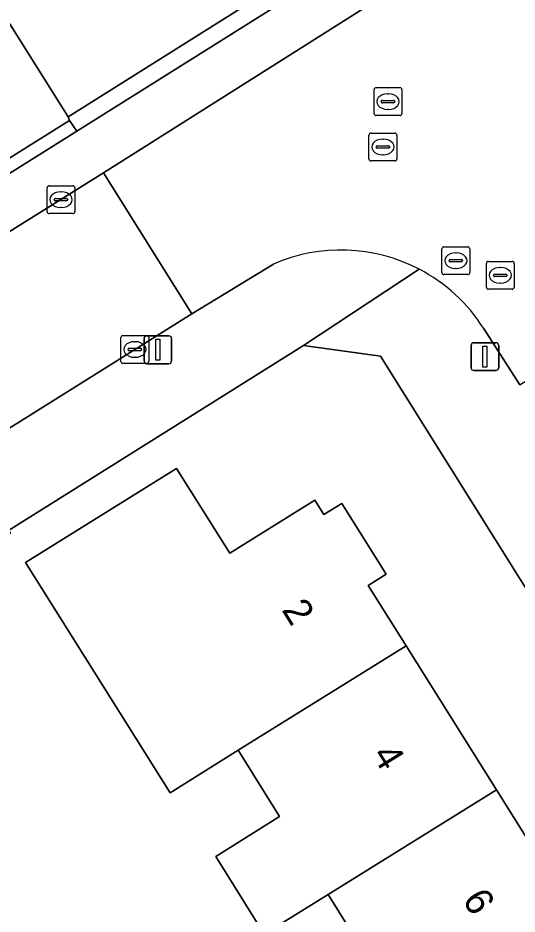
# Model space of a CAD drawing. Extents: x 159352 to 160617, y 385888 to 387323.
# Drawn here: x 159664.19 to 159682.11, y 386145.65 to 386177.82 of the extents above; entities that cross this region are included whole.
import ezdxf

# ---------------------------------------------------------------- set-up
doc = ezdxf.new("R2010")
doc.units = 0
for name, color, linetype in [('IMGEO_Erf', 7, 'Continuous'), ('IMGEO_Groenvoorziening', 7, 'Continuous'), ('IMGEO_Kolk', 7, 'Continuous'), ('IMGEO_Lichtmast', 7, 'Continuous'), ('IMGEO_Pand', 7, 'Continuous'), ('IMGEO_Pand_nummerreeks', 7, 'Continuous'), ('IMGEO_Parkeervlak_open', 7, 'Continuous'), ('IMGEO_Rijbaan_lokaal_open', 7, 'Continuous'), ('IMGEO_Rioolput', 7, 'Continuous'), ('IMGEO_Voetpad_open', 7, 'Continuous')]:
    doc.layers.add(name, color=color, linetype=linetype)

msp = doc.modelspace()

# ---------------------------------------------------------------- linework, layer by layer
at = {"layer": 'IMGEO_Erf'}
for points in [[(159712.934, 386108.61), (159677.208, 386165.677), (159674.448, 386166.054), (159663.861, 386159.423), (159663.923, 386159.326), (159657.127, 386155.101), (159662.969, 386145.784), (159661.381, 386144.772)], [(159678.55, 386141.18), (159675.326, 386146.356), (159673.029, 386144.926), (159671.294, 386147.714), (159673.587, 386149.149), (159672.103, 386151.532), (159669.661, 386150.002), (159664.466, 386158.268), (159669.886, 386161.642), (159671.796, 386158.603), (159674.849, 386160.506), (159675.173, 386159.989), (159675.818, 386160.391), (159677.412, 386157.849), (159676.767, 386157.447), (159678.126, 386155.28), (159681.365, 386150.113), (159684.605, 386144.946)]]:
    msp.add_lwpolyline(points, dxfattribs=at)
at = {"layer": 'IMGEO_Groenvoorziening'}
msp.add_lwpolyline([(159665.998, 386174.271), (159679.843, 386182.982), (159678.601, 386185.01), (159672.385, 386182.329), (159672.791, 386181.378), (159671.129, 386180.658), (159670.692, 386181.586), (159669.578, 386181.115), (159663.38, 386178.426)], close=True, dxfattribs=at)
at = {"layer": 'IMGEO_Kolk'}
for p, q in [((159665.239, 386170.867), (159665.239, 386171.719)), ((159665.314, 386171.793), (159666.166, 386171.793)), ((159665.727, 386171.573), (159665.752, 386171.573)), ((159666.24, 386171.719), (159666.24, 386170.867)), ((159665.498, 386171.287), (159665.498, 386171.299)), ((159665.936, 386171.25), (159665.538, 386171.25)), ((159665.541, 386171.336), (159665.939, 386171.336)), ((159665.982, 386171.299), (159665.982, 386171.287)), ((159665.75, 386171.013), (159665.725, 386171.013)), ((159666.166, 386170.793), (159665.314, 386170.793)), ((159667.89, 386165.49), (159667.89, 386166.342)), ((159667.965, 386166.416), (159668.817, 386166.416)), ((159668.891, 386166.342), (159668.891, 386165.49)), ((159668.378, 386166.196), (159668.403, 386166.196)), ((159668.149, 386165.91), (159668.149, 386165.922)), ((159668.587, 386165.873), (159668.189, 386165.873)), ((159668.192, 386165.959), (159668.59, 386165.959)), ((159668.633, 386165.922), (159668.633, 386165.91)), ((159668.817, 386165.416), (159667.965, 386165.416)), ((159668.401, 386165.636), (159668.376, 386165.636))]:
    msp.add_line(p, q, dxfattribs=at)
for points in [[(159665.239, 386170.867), (159665.239, 386171.719)], [(159665.314, 386171.793), (159666.166, 386171.793)], [(159666.24, 386171.719), (159666.24, 386170.867)], [(159666.166, 386170.793), (159665.314, 386170.793)], [(159667.89, 386165.49), (159667.89, 386166.342)], [(159667.965, 386166.416), (159668.817, 386166.416)], [(159668.891, 386166.342), (159668.891, 386165.49)], [(159668.817, 386165.416), (159667.965, 386165.416)]]:
    msp.add_lwpolyline(points, dxfattribs=at)
for centre, radius, start, end in [((159665.316, 386171.717), 0.0765, 91.552, 178.448), ((159665.316, 386171.717), 0.0765, 91.552, 178.448), ((159666.164, 386171.717), 0.0765, 1.552, 88.448), ((159666.164, 386171.717), 0.0765, 1.552, 88.448), ((159665.538, 386171.296), 0.0403, 85.8775, 175.7526), ((159665.535, 386171.286), 0.0366, 178.938, 274.7102), ((159665.939, 386171.293), 0.043, 264.8664, 352.4533), ((159665.943, 386171.298), 0.0386, 1.7309, 96.639), ((159665.316, 386170.869), 0.0765, 181.552, 268.448), ((159665.316, 386170.869), 0.0765, 181.552, 268.448), ((159666.164, 386170.869), 0.0765, 271.552, 358.448), ((159666.164, 386170.869), 0.0765, 271.552, 358.448), ((159667.967, 386166.34), 0.0765, 91.552, 178.448), ((159667.967, 386166.34), 0.0765, 91.552, 178.448), ((159668.815, 386166.34), 0.0765, 1.552, 88.448), ((159668.815, 386166.34), 0.0765, 1.552, 88.448), ((159668.189, 386165.919), 0.0403, 85.8775, 175.7526), ((159668.186, 386165.909), 0.0366, 178.938, 274.7102), ((159668.59, 386165.916), 0.043, 264.8664, 352.4533), ((159668.594, 386165.921), 0.0386, 1.7309, 96.639), ((159667.967, 386165.492), 0.0765, 181.552, 268.448), ((159667.967, 386165.492), 0.0765, 181.552, 268.448), ((159668.815, 386165.492), 0.0765, 271.552, 358.448), ((159668.815, 386165.492), 0.0765, 271.552, 358.448)]:
    msp.add_arc(centre, radius, start, end, dxfattribs=at)
for centre, major_axis, ratio, start_param, end_param in [((159665.726, 386171.293), (-0.387, 0.002), 0.722429, 4.712389, 7.853982), ((159665.751, 386171.293), (-0.39, 0.002), 0.717154, 1.570796, 4.712389), ((159668.377, 386165.916), (-0.387, 0.002), 0.722429, 4.712389, 7.853982), ((159668.402, 386165.916), (-0.39, 0.002), 0.717154, 1.570796, 4.712389)]:
    msp.add_ellipse(centre, major_axis=major_axis, ratio=ratio, start_param=start_param, end_param=end_param, dxfattribs=at)
at = {"layer": 'IMGEO_Lichtmast'}
for p, q in [((159668.82, 386166.407), (159669.61, 386166.407)), ((159669.61, 386166.407), (159668.82, 386166.407)), ((159668.72, 386165.507), (159668.72, 386166.307)), ((159668.72, 386166.307), (159668.72, 386165.507)), ((159669.71, 386166.307), (159669.71, 386165.507)), ((159669.71, 386165.507), (159669.71, 386166.307)), ((159680.459, 386165.261), (159680.459, 386166.061)), ((159680.459, 386166.061), (159680.459, 386165.261)), ((159680.559, 386166.161), (159681.349, 386166.161)), ((159681.349, 386166.161), (159680.559, 386166.161)), ((159681.449, 386166.061), (159681.449, 386165.261)), ((159681.449, 386165.261), (159681.449, 386166.061)), ((159669.61, 386165.407), (159668.82, 386165.407)), ((159668.82, 386165.407), (159669.61, 386165.407)), ((159681.349, 386165.161), (159680.559, 386165.161)), ((159680.559, 386165.161), (159681.349, 386165.161))]:
    msp.add_line(p, q, dxfattribs=at)
for points in [[(159669.14, 386166.282), (159669.29, 386166.282), (159669.29, 386165.532), (159669.14, 386165.532), (159669.14, 386166.282)], [(159680.879, 386166.036), (159681.029, 386166.036), (159681.029, 386165.286), (159680.879, 386165.286), (159680.879, 386166.036)]]:
    msp.add_lwpolyline(points, dxfattribs=at)
for centre, start, end in [((159668.82, 386166.307), 90, 180), ((159668.82, 386166.307), 90, 180), ((159669.61, 386166.307), 0, 90), ((159669.61, 386166.307), 360, 90), ((159680.559, 386166.061), 90, 180), ((159680.559, 386166.061), 90, 180), ((159681.349, 386166.061), 0, 90), ((159681.349, 386166.061), 360, 90), ((159668.82, 386165.507), 180, 270), ((159668.82, 386165.507), 180, 270), ((159669.61, 386165.507), 270, 0), ((159669.61, 386165.507), 270, 0), ((159680.559, 386165.261), 180, 270), ((159680.559, 386165.261), 180, 270), ((159681.349, 386165.261), 270, 0), ((159681.349, 386165.261), 270, 0)]:
    msp.add_arc(centre, 0.1, start, end, dxfattribs=at)
at = {"layer": 'IMGEO_Pand'}
for points in [[(159678.126, 386155.28), (159676.767, 386157.447), (159677.412, 386157.849), (159675.818, 386160.391), (159675.173, 386159.989), (159674.849, 386160.506), (159671.796, 386158.603), (159669.886, 386161.642), (159664.466, 386158.268), (159669.661, 386150.002), (159672.103, 386151.532)], [(159681.365, 386150.113), (159678.126, 386155.28), (159672.103, 386151.532), (159673.587, 386149.149), (159671.294, 386147.714), (159673.029, 386144.926), (159675.326, 386146.356)], [(159675.326, 386146.356), (159678.55, 386141.18), (159684.605, 386144.946), (159681.365, 386150.113)]]:
    msp.add_lwpolyline(points, close=True, dxfattribs=at)
at = {"layer": 'IMGEO_Parkeervlak_open'}
for points in [[(159694.982, 386191.739), (159692.137, 386189.957), (159683.351, 386184.43), (159680.171, 386182.463), (159666.308, 386173.758), (159663.117, 386171.76), (159649.085, 386162.993), (159645.879, 386160.999), (159629.498, 386150.732), (159629.323, 386150.614)], [(159667.269, 386172.261), (159686.801, 386184.624), (159698.284, 386191.67)], [(159628.085, 386147.762), (159667.269, 386172.261)]]:
    msp.add_lwpolyline(points, dxfattribs=at)
at = {"layer": 'IMGEO_Rijbaan_lokaal_open'}
for points in [[(159685.663, 386176.667), (159690.037, 386179.433), (159686.801, 386184.624), (159667.269, 386172.261), (159670.441, 386167.202), (159673.365, 386168.979)], [(159680.899, 386166.685), (159682.211, 386164.651), (159685.102, 386166.476), (159683.833, 386168.497)]]:
    msp.add_lwpolyline(points, dxfattribs=at)
msp.add_lwpolyline([(159648.997, 386153.776), (159651.127, 386155.109), (159653.753, 386156.753), (159670.441, 386167.202), (159667.269, 386172.261), (159628.085, 386147.762), (159631.34, 386142.72), (159646.177, 386152.01)], close=True, dxfattribs=at)
for centre, radius, start, end in [((159675.792, 386163.428), 6.059, 62.3802, 113.6164), ((159675.787, 386163.426), 6.063, 32.5164, 62.3409)]:
    msp.add_arc(centre, radius, start, end, dxfattribs=at)
at = {"layer": 'IMGEO_Rioolput'}
for p, q in [((159676.976, 386174.39), (159676.976, 386175.242)), ((159677.051, 386175.316), (159677.903, 386175.316)), ((159677.464, 386175.096), (159677.489, 386175.096)), ((159677.977, 386175.242), (159677.977, 386174.39)), ((159677.235, 386174.81), (159677.235, 386174.822)), ((159677.673, 386174.773), (159677.275, 386174.773)), ((159677.278, 386174.859), (159677.676, 386174.859)), ((159677.719, 386174.822), (159677.719, 386174.81)), ((159677.487, 386174.536), (159677.462, 386174.536)), ((159677.903, 386174.316), (159677.051, 386174.316)), ((159676.794, 386172.758), (159676.794, 386173.61)), ((159676.869, 386173.684), (159677.721, 386173.684)), ((159677.282, 386173.464), (159677.307, 386173.464)), ((159677.795, 386173.61), (159677.795, 386172.758)), ((159677.053, 386173.178), (159677.053, 386173.19)), ((159677.491, 386173.141), (159677.093, 386173.141)), ((159677.096, 386173.227), (159677.494, 386173.227)), ((159677.537, 386173.19), (159677.537, 386173.178)), ((159677.305, 386172.904), (159677.28, 386172.904)), ((159677.721, 386172.684), (159676.869, 386172.684)), ((159679.486, 386169.604), (159680.338, 386169.604)), ((159679.411, 386168.678), (159679.411, 386169.53)), ((159679.899, 386169.384), (159679.924, 386169.384)), ((159680.412, 386169.53), (159680.412, 386168.678)), ((159679.67, 386169.098), (159679.67, 386169.11)), ((159680.108, 386169.061), (159679.71, 386169.061)), ((159679.713, 386169.147), (159680.111, 386169.147)), ((159680.154, 386169.11), (159680.154, 386169.098)), ((159681.006, 386168.154), (159681.006, 386169.006)), ((159681.081, 386169.08), (159681.933, 386169.08)), ((159682.007, 386169.006), (159682.007, 386168.154)), ((159680.338, 386168.604), (159679.486, 386168.604)), ((159679.922, 386168.824), (159679.897, 386168.824)), ((159681.308, 386168.623), (159681.706, 386168.623)), ((159681.494, 386168.86), (159681.519, 386168.86)), ((159681.265, 386168.574), (159681.265, 386168.586)), ((159681.703, 386168.537), (159681.305, 386168.537)), ((159681.517, 386168.3), (159681.492, 386168.3)), ((159681.749, 386168.586), (159681.749, 386168.574)), ((159681.933, 386168.08), (159681.081, 386168.08))]:
    msp.add_line(p, q, dxfattribs=at)
for points in [[(159676.976, 386174.39), (159676.976, 386175.242)], [(159677.051, 386175.316), (159677.903, 386175.316)], [(159677.977, 386175.242), (159677.977, 386174.39)], [(159677.903, 386174.316), (159677.051, 386174.316)], [(159676.794, 386172.758), (159676.794, 386173.61)], [(159676.869, 386173.684), (159677.721, 386173.684)], [(159677.795, 386173.61), (159677.795, 386172.758)], [(159677.721, 386172.684), (159676.869, 386172.684)], [(159679.486, 386169.604), (159680.338, 386169.604)], [(159679.411, 386168.678), (159679.411, 386169.53)], [(159680.412, 386169.53), (159680.412, 386168.678)], [(159681.006, 386168.154), (159681.006, 386169.006)], [(159681.081, 386169.08), (159681.933, 386169.08)], [(159682.007, 386169.006), (159682.007, 386168.154)], [(159680.338, 386168.604), (159679.486, 386168.604)], [(159681.933, 386168.08), (159681.081, 386168.08)]]:
    msp.add_lwpolyline(points, dxfattribs=at)
for centre, radius, start, end in [((159677.053, 386175.24), 0.0765, 91.552, 178.448), ((159677.053, 386175.24), 0.0765, 91.552, 178.448), ((159677.901, 386175.24), 0.0765, 1.552, 88.448), ((159677.901, 386175.24), 0.0765, 1.552, 88.448), ((159677.275, 386174.819), 0.0403, 85.8775, 175.7526), ((159677.272, 386174.809), 0.0366, 178.938, 274.7102), ((159677.676, 386174.816), 0.043, 264.8664, 352.4533), ((159677.68, 386174.821), 0.0386, 1.7309, 96.639), ((159677.053, 386174.392), 0.0765, 181.552, 268.448), ((159677.053, 386174.392), 0.0765, 181.552, 268.448), ((159677.901, 386174.392), 0.0765, 271.552, 358.448), ((159677.901, 386174.392), 0.0765, 271.552, 358.448), ((159676.871, 386173.608), 0.0765, 91.552, 178.448), ((159676.871, 386173.608), 0.0765, 91.552, 178.448), ((159677.719, 386173.608), 0.0765, 1.552, 88.448), ((159677.719, 386173.608), 0.0765, 1.552, 88.448), ((159677.093, 386173.187), 0.0403, 85.8775, 175.7526), ((159677.09, 386173.177), 0.0366, 178.938, 274.7102), ((159677.494, 386173.184), 0.043, 264.8664, 352.4533), ((159677.498, 386173.189), 0.0386, 1.7309, 96.639), ((159676.871, 386172.76), 0.0765, 181.552, 268.448), ((159676.871, 386172.76), 0.0765, 181.552, 268.448), ((159677.719, 386172.76), 0.0765, 271.552, 358.448), ((159677.719, 386172.76), 0.0765, 271.552, 358.448), ((159679.488, 386169.528), 0.0765, 91.552, 178.448), ((159679.488, 386169.528), 0.0765, 91.552, 178.448), ((159680.336, 386169.528), 0.0765, 1.552, 88.448), ((159680.336, 386169.528), 0.0765, 1.552, 88.448), ((159679.71, 386169.107), 0.0403, 85.8775, 175.7526), ((159679.707, 386169.097), 0.0366, 178.938, 274.7102), ((159680.111, 386169.104), 0.043, 264.8664, 352.4533), ((159680.115, 386169.109), 0.0386, 1.7309, 96.639), ((159681.083, 386169.004), 0.0765, 91.552, 178.448), ((159681.083, 386169.004), 0.0765, 91.552, 178.448), ((159681.931, 386169.004), 0.0765, 1.552, 88.448), ((159681.931, 386169.004), 0.0765, 1.552, 88.448), ((159679.488, 386168.68), 0.0765, 181.552, 268.448), ((159679.488, 386168.68), 0.0765, 181.552, 268.448), ((159680.336, 386168.68), 0.0765, 271.552, 358.448), ((159680.336, 386168.68), 0.0765, 271.552, 358.448), ((159681.305, 386168.583), 0.0403, 85.8775, 175.7526), ((159681.71, 386168.585), 0.0386, 1.7309, 96.639), ((159681.302, 386168.573), 0.0366, 178.938, 274.7102), ((159681.706, 386168.58), 0.043, 264.8664, 352.4533), ((159681.083, 386168.156), 0.0765, 181.552, 268.448), ((159681.083, 386168.156), 0.0765, 181.552, 268.448), ((159681.931, 386168.156), 0.0765, 271.552, 358.448), ((159681.931, 386168.156), 0.0765, 271.552, 358.448)]:
    msp.add_arc(centre, radius, start, end, dxfattribs=at)
for centre, major_axis, ratio, start_param, end_param in [((159677.463, 386174.816), (-0.387, 0.002), 0.722429, 4.712389, 7.853982), ((159677.488, 386174.816), (-0.39, 0.002), 0.717154, 1.570796, 4.712389), ((159677.281, 386173.184), (-0.387, 0.002), 0.722429, 4.712389, 7.853982), ((159677.306, 386173.184), (-0.39, 0.002), 0.717154, 1.570796, 4.712389), ((159679.898, 386169.104), (-0.387, 0.002), 0.722429, 4.712389, 7.853982), ((159679.923, 386169.104), (-0.39, 0.002), 0.717154, 1.570796, 4.712389), ((159681.493, 386168.58), (-0.387, 0.002), 0.722429, 4.712389, 7.853982), ((159681.518, 386168.58), (-0.39, 0.002), 0.717154, 1.570796, 4.712389)]:
    msp.add_ellipse(centre, major_axis=major_axis, ratio=ratio, start_param=start_param, end_param=end_param, dxfattribs=at)
at = {"layer": 'IMGEO_Voetpad_open'}
for points in [[(159662.86, 386172.145), (159666.048, 386174.133), (159665.998, 386174.271), (159663.38, 386178.426), (159669.578, 386181.115), (159670.692, 386181.586), (159671.129, 386180.658), (159672.791, 386181.378), (159672.385, 386182.329), (159678.601, 386185.01), (159679.843, 386182.982), (159679.947, 386182.816), (159683.126, 386184.832), (159683.351, 386184.43), (159692.137, 386189.957), (159691.793, 386190.467), (159685.357, 386186.443), (159684.781, 386187.668), (159691.207, 386190.458), (159698.352, 386193.525), (159698.969, 386192.653), (159702.158, 386194.63), (159702.417, 386194.251), (159725.377, 386208.588)], [(159673.365, 386168.979), (159670.441, 386167.202), (159653.753, 386156.753), (159654.266, 386155.932), (159651.638, 386154.291), (159651.127, 386155.109), (159648.997, 386153.776), (159649.507, 386152.96), (159646.684, 386151.198), (159646.177, 386152.01), (159631.34, 386142.72), (159628.856, 386141.148), (159626.028, 386139.36)], [(159657.127, 386155.101), (159663.923, 386159.326), (159663.861, 386159.423), (159674.448, 386166.054), (159678.601, 386168.796)], [(159678.601, 386168.796), (159674.448, 386166.054), (159677.208, 386165.677), (159712.934, 386108.61), (159713.923, 386107.031), (159717.083, 386101.983), (159727.834, 386084.857), (159727.06, 386082.254), (159731.503, 386085.122)], [(159682.211, 386164.651), (159680.899, 386166.685)]]:
    msp.add_lwpolyline(points, dxfattribs=at)
for points in [[(159680.171, 386182.463), (159679.947, 386182.816), (159679.843, 386182.982), (159665.998, 386174.271), (159666.048, 386174.133), (159666.308, 386173.758)], [(159663.117, 386171.76), (159666.308, 386173.758), (159666.048, 386174.133), (159662.86, 386172.145)]]:
    msp.add_lwpolyline(points, close=True, dxfattribs=at)
for centre, radius, start, end in [((159675.792, 386163.428), 6.059, 62.3802, 113.6164), ((159675.787, 386163.426), 6.063, 32.5164, 62.3409)]:
    msp.add_arc(centre, radius, start, end, dxfattribs=at)

# ---------------------------------------------------------------- texts
at = {"layer": 'IMGEO_Pand_nummerreeks'}
for s, p in [('2', (159673.644, 386156.567)), ('4', (159676.885, 386151.363)), ('6', (159680.124, 386146.161))]:
    msp.add_text(s, height=1, rotation=301.9122, dxfattribs=at).set_placement(p)

doc.saveas('drawing.dxf')
